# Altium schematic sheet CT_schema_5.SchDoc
size 236 x 243 mm
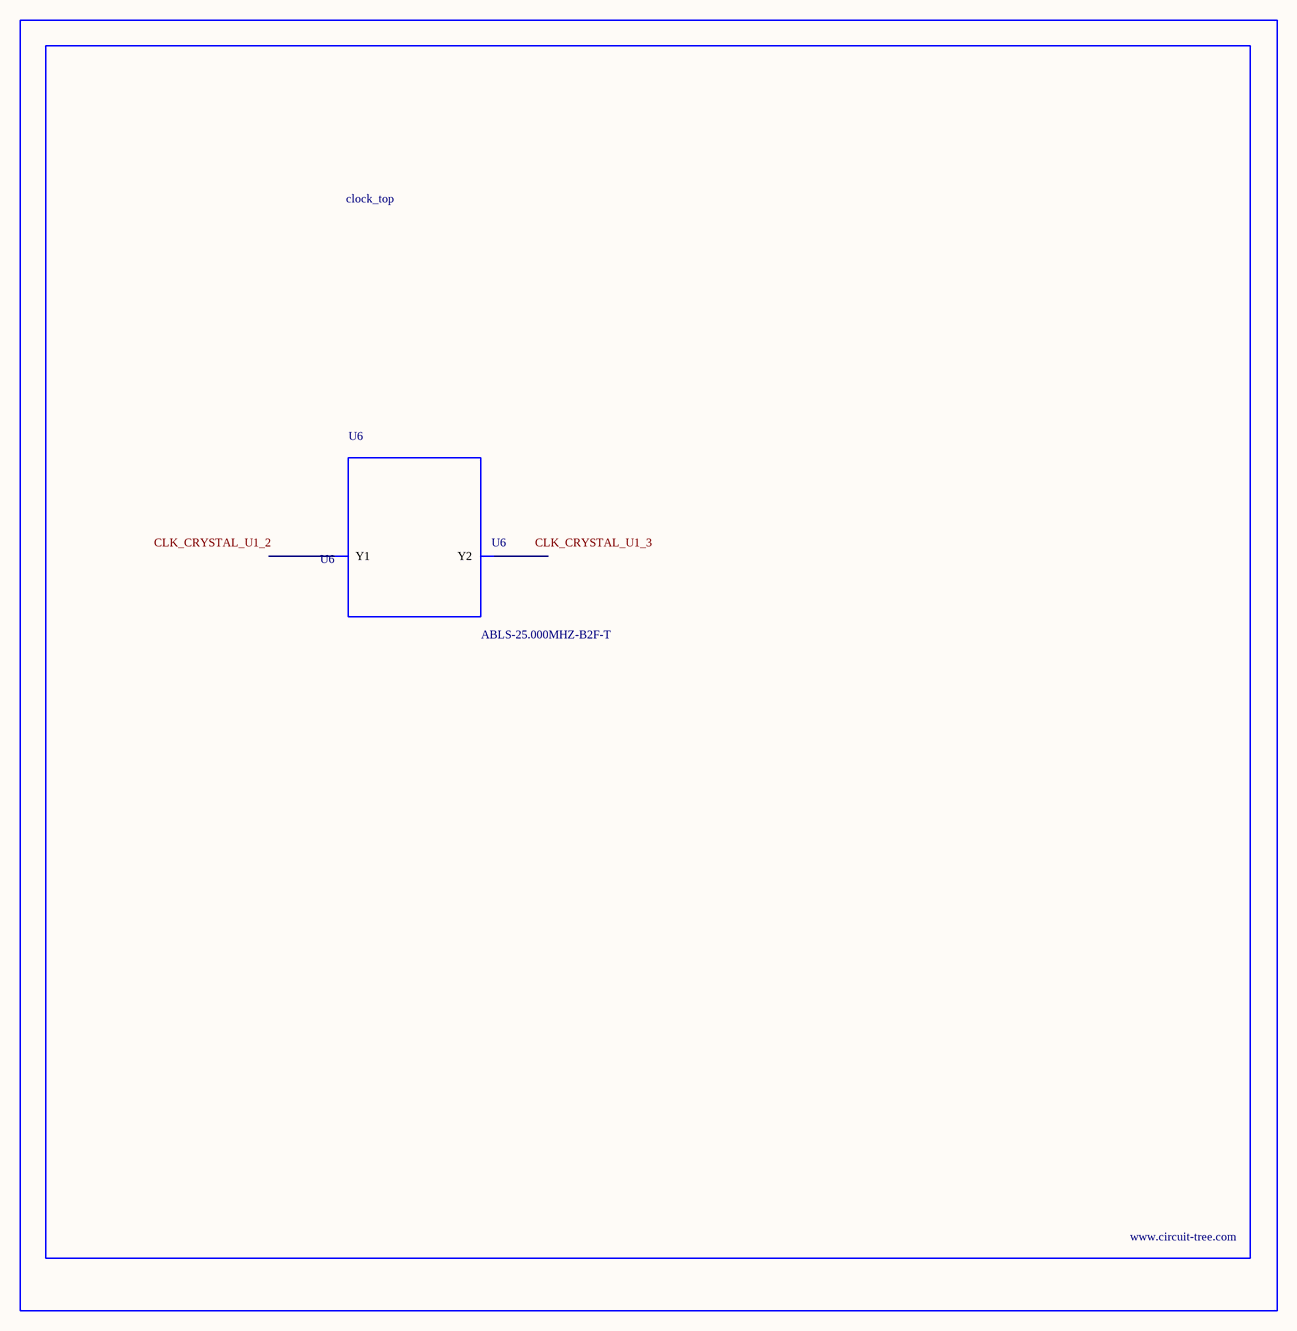
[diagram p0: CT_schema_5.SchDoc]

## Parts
BORDER4  (no value)
U6  ABLS-25.000MHZ-B2F-T  [ABLS-25.000MHZ-B2F-T]

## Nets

Not connected (* = marked no-connect by the designer): U6 1(Y1) 2(Y2)

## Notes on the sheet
- Labels drawn without touching a wire or pin: CLK_CRYSTAL_U1_2, CLK_CRYSTAL_U1_3

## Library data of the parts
BORDER4 = BORDER_PAGE4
